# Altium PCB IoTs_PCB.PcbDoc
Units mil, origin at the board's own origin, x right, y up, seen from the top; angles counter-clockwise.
Board outline 3940 x 3935 mil, 2 copper layers (Top Layer, Bottom Layer); 12 components, 13 nets, 57 pads, 0 vias.
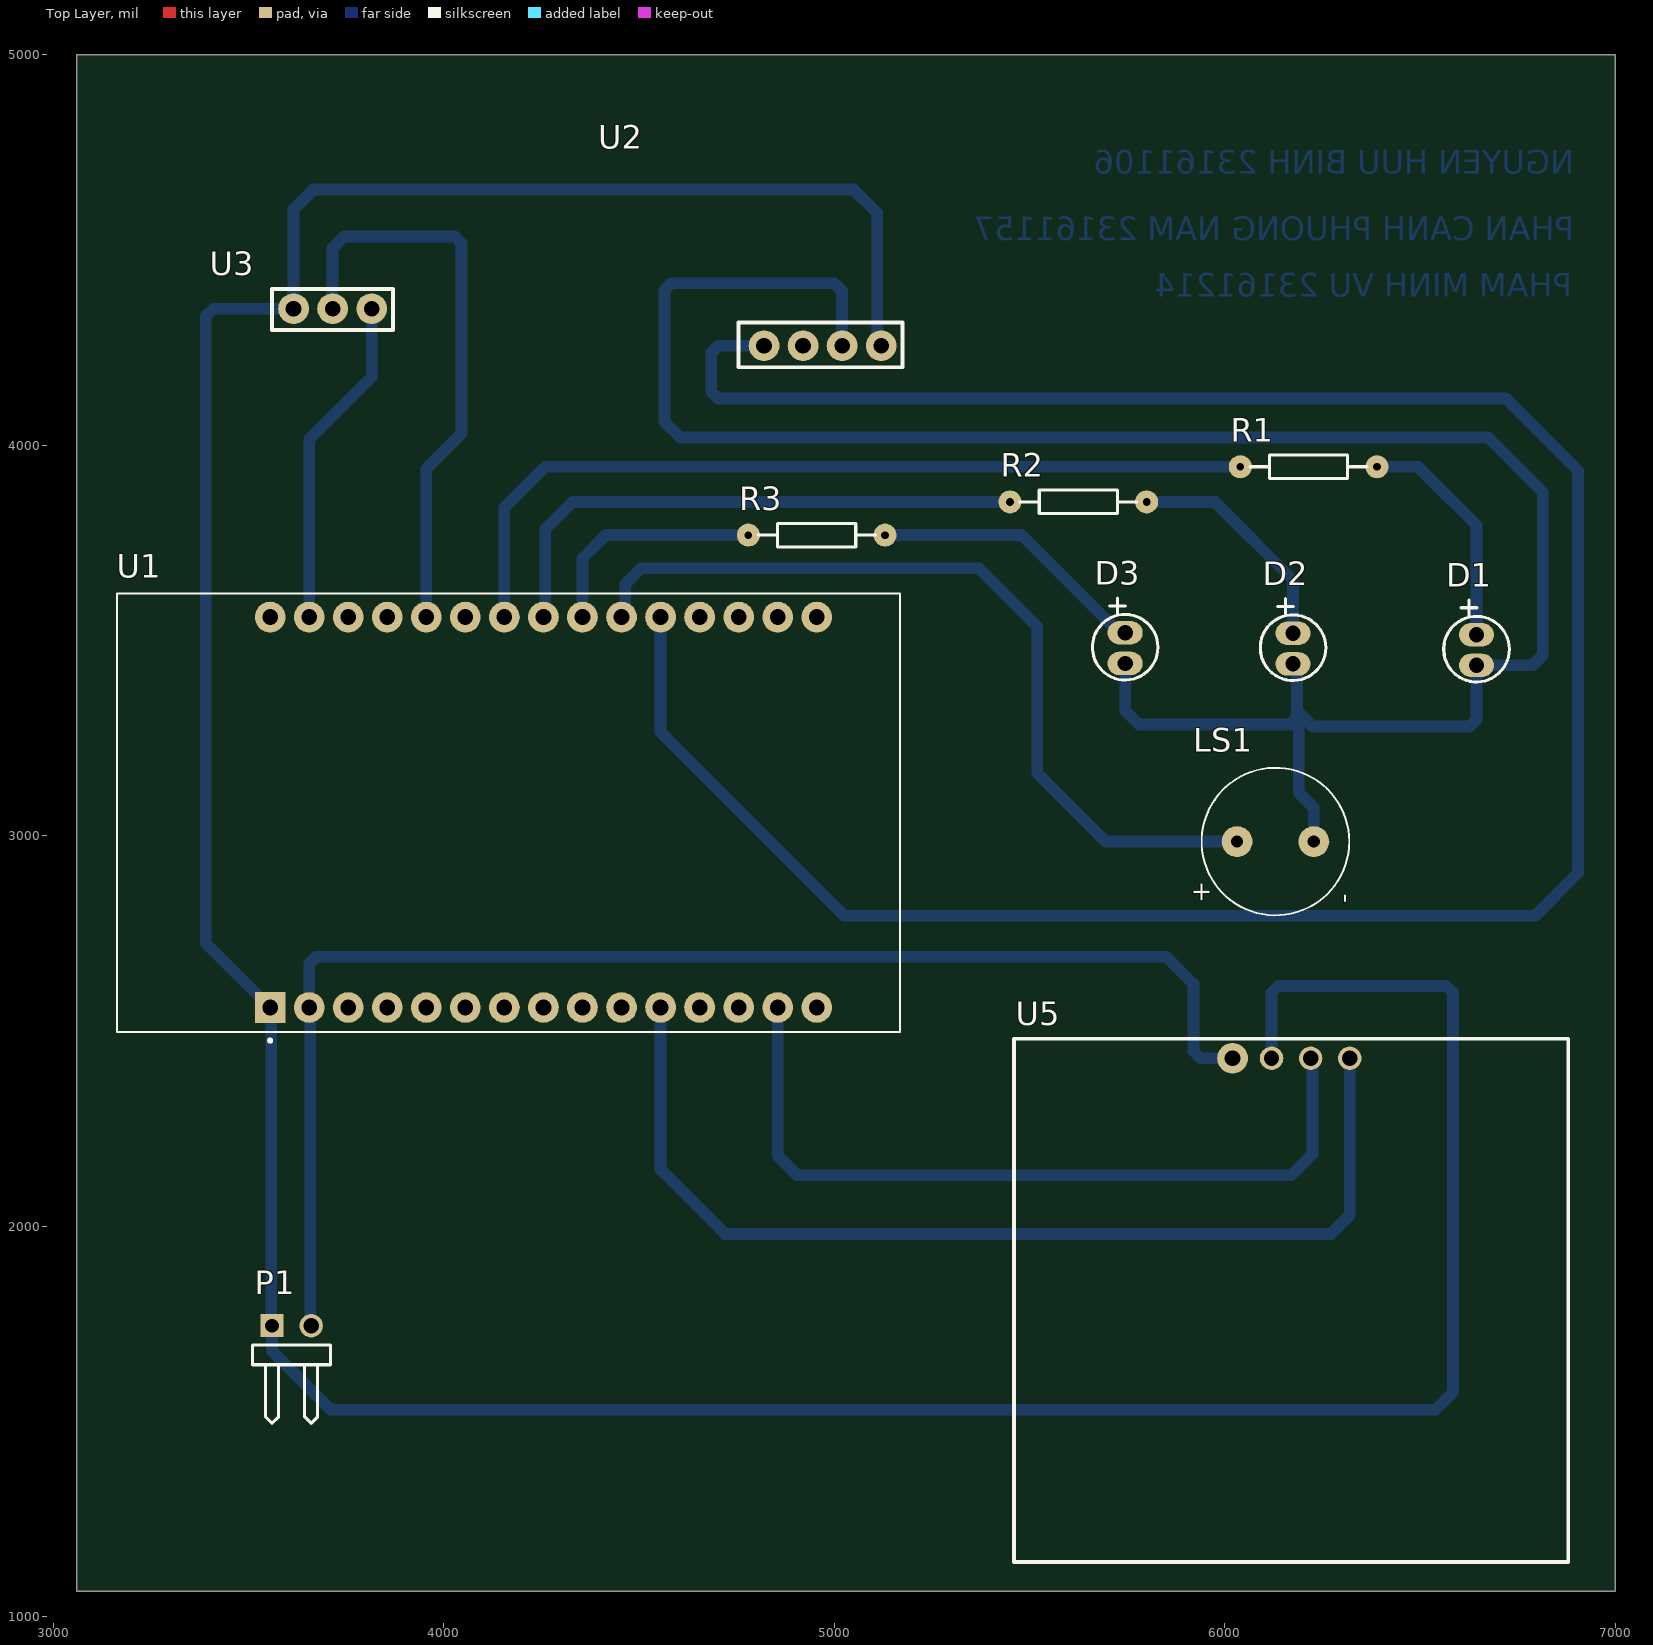
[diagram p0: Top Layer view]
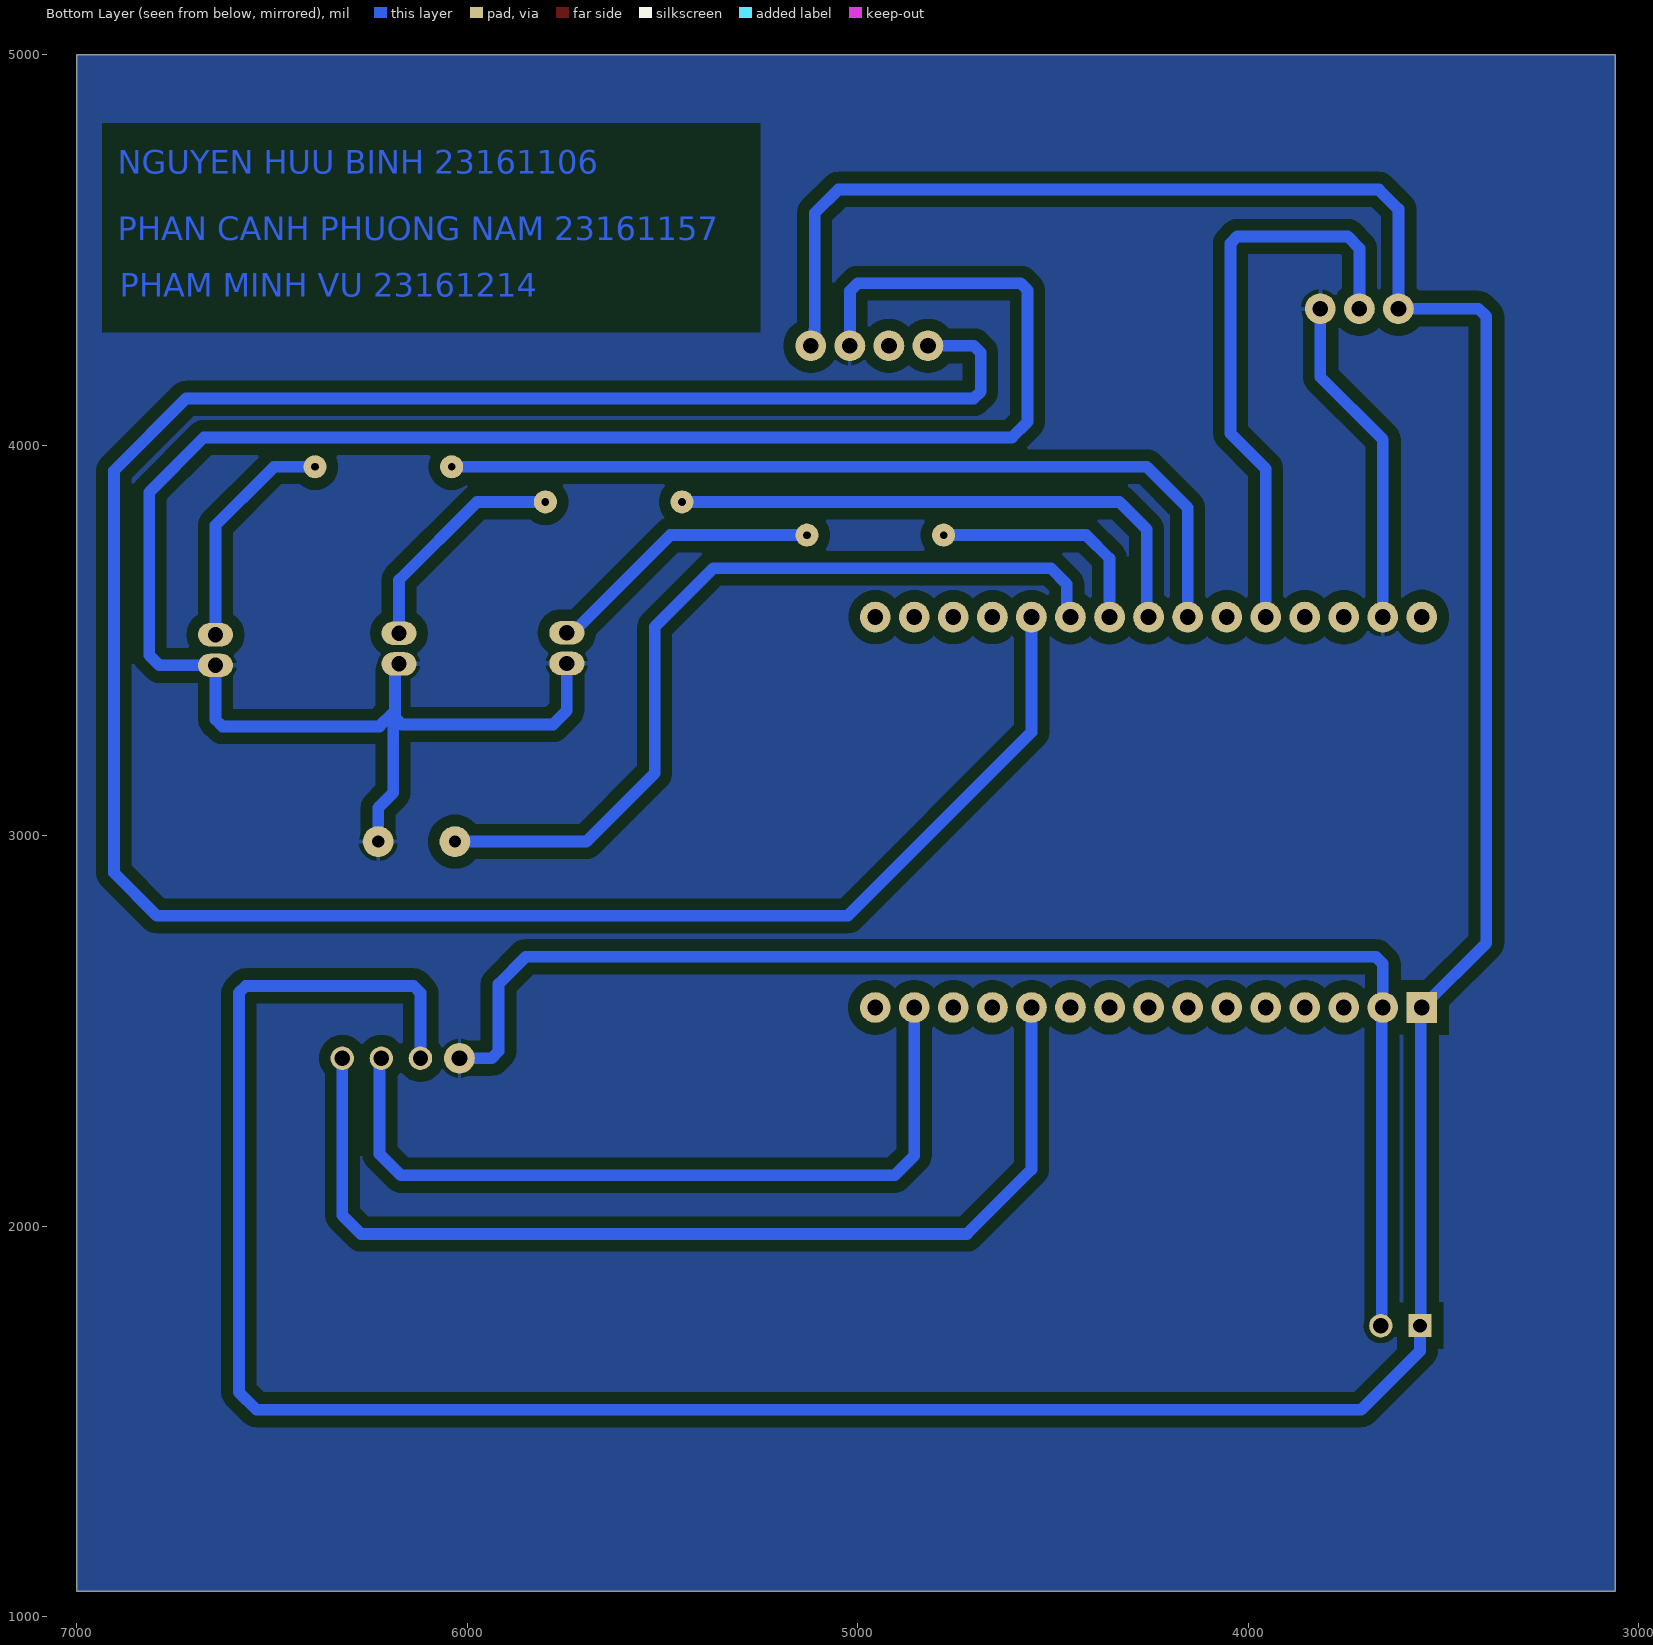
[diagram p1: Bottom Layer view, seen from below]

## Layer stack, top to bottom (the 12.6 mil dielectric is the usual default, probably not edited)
Top Solder: solder mask 0.4, Solder Resist, Dk 3.5
Top Layer: signal copper 1.4
Dielectric 1: dielectric 12.6, FR-4, Dk 4.8
Bottom Layer: signal copper 1.4
Bottom Solder: solder mask 0.4, Solder Resist, Dk 3.5

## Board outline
3060,1065 7000,1065 7000,5000 3060,5000

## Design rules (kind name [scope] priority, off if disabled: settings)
Clearance [All] p1: gap=10 ignorepadtopadclearanceinfootprint=FALSE except(30: Arc-Fill Arc-Poly Arc-Region Track-Fill Track-Poly Track-Region SMDPad-Fill SMDPad-Poly SMDPad-Region THPad-Fill THPad-Poly THPad-Region Via-Fill Via-Poly Via-Region Fill-Fill Fill-Poly Fill-Region Poly-Poly Poly-Region Region-Region)
PolygonConnect [All] p1: connectstyle=Relief reliefconductorwidth=10 reliefentries=4 polygonreliefangle="90 Angle" airgapwidth=10
RoutingLayers [All] p1: top layer_v5=FALSE bottom layer_v5=TRUE
RoutingVias [All] p1: holewidth=28 width=50 viastyle="Through Hole" minholewidth=28 minwidth=50 maxholewidth=28 maxwidth=50
SolderMaskExpansion [All] p1: expansion=4 istentingtop=FALSE
Width [All] p1: maxlimit=50 minlimit=28 preferedwidth=30
29 further rules are at their usual default settings.

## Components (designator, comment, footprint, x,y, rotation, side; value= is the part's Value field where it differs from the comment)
D1 "LED" CAP10UF 6645,3436.26 r90 top
D2 "LED" CAP10UF 6175,3440 r90 top
D3 "LED" CAP10UF 5745,3441.26 r90 top
LS1 "CMI-9605IC-0580T" CUI_CMI-9605IC-0580T 6130,2985 r90 top
P1 "Header 2H" HDR1X2H 3560,1745 r0 top
R1 "220" R1/6W 6215,3945 r0 top value="R1/4W - 1K"
R2 "220" R1/6W 5625,3855 r0 top value="R1/4W - 1K"
R3 "220" R1/6W 4955,3770 r0 top value="R1/4W - 1K"
U1 "ESP32_DEVKIT_V1" ESP32_DEVKIT_V1 4190.83,3045 r90 top
U2 "MQ_135" MQ_135 4820,4255 r0 top
U3 "DHT11" DHT11 3615,4350 r0 top
U5 "LCD OLED SSD1306" "LCD SH1106" 6235,1735 r0 top

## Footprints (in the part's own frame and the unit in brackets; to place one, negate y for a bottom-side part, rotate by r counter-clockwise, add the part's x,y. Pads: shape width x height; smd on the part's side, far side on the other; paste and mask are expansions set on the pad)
CAP10UF [mil]
  oval 60x90 hole 39.37 unplated: 1(78.74,0) 2(0,0)
  silkscreen extent -42,-84 167,84
CUI_CMI-9605IC-0580T [mm]
  round 2 hole 0.8: N(0,-2.5) P(0,2.5)
  silkscreen extent -4.8,-4.8 4.8,4.8, body extent -4.8,-4.8 4.8,4.8
DHT11 [mm]
  round 2 hole 1.02: 1(0,0) 2(2.54,0) 3(5.08,0)
  silkscreen extent -1.4,-1.4 6.48,1.27, body extent -5.71,-7.49 10.29,1.01, height 24.09
ESP32_DEVKIT_V1 [mm]
  rect 2x2 / inner round 2 / far side rect 2x2 hole 1.02: 1(-12.319,16.15)
  round 2 hole 1.02: 2(-12.319,13.61) 3(-12.319,11.07) 4(-12.319,8.53) 5(-12.319,5.99) 6(-12.319,3.45) 7(-12.319,0.91) 8(-12.319,-1.63) 9(-12.319,-4.17) 10(-12.319,-6.71) 11(-12.319,-9.25) 12(-12.319,-11.79) 13(-12.319,-14.33) 14(-12.319,-16.87) 15(-12.319,-19.41) 16(13.081,-19.41) 17(13.081,-16.87) 18(13.081,-14.33) 19(13.081,-11.79) 20(13.081,-9.25) 21(13.081,-6.71) 22(13.081,-4.17) 23(13.081,-1.63) 24(13.081,0.91) 25(13.081,3.45) 26(13.081,5.99) 27(13.081,8.53) 28(13.081,11.07) 29(13.081,13.61) 30(13.081,16.15)
  silkscreen extent -14.57,-24.84 14.61,26.11
HDR1X2H [mm] "Connector; Header; 2 Position; Right Angle"
  rect 1.5x1.5 hole 0.9: 1(0,0)
  round 1.524 hole 1.02: 2(2.54,0)
  silkscreen extent -1.27,-6.35 3.81,-1.27, body extent -1.27,-7 3.81,1.27, height 4.33
"LCD SH1106" [mil]
  round 60 hole 39.37: 1(85,695) 2(-15,695) 3(-115,695)
  round 78.74 hole 40.16: 4(-215,695)
  silkscreen extent -775,-595 645,745, body extent -774,-594 644,744, height 378
MQ_135 [mm]
  round 2 hole 1.02: 1(7.62,0) 2(5.08,0) 3(2.54,0) 4(0,0)
  silkscreen extent -1.65,-1.4 9.02,1.52, body extent -6.75,-4.99 14.25,18.01, height 1.5
R1/6W [mm]
  round 1.5 hole 0.5: 1(-4.445,0) 2(4.445,0)
  silkscreen extent -3.81,-0.76 3.81,0.76

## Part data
LS1: "9.6 mm, 5 Vdc, 80 dB, Through Hole, Driving Circuit, Magnetic Audio Indicator Buzzer", Package=Package
P1: "Header, 2-Pin, Right Angle"
R1 R2 R3: library part Res, "Resistor 1/4W"
U5: library part "LCD SH1106"

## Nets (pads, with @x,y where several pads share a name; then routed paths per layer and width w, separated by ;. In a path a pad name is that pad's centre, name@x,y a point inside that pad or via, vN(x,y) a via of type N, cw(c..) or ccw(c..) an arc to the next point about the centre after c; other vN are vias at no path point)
A0: U1.20 U2.4 | length 6461.3
  Bottom Layer w30: U1.20 4555,3265 5025,2795 6795,2795 6905,2905 6905,3935 6720,4120 4702.57,4120 4685,4137.57 4685,4237.43 4702.57,4255 U2.4
DAT: U1.26 U3.2 | length 1499.4
  Bottom Layer w30: U3.2 3715,4505 3745,4535 4027.43,4535 4045,4517.43 4045,4030 3955,3940 U1.26
GND: D1.2 D2.2 D3.2 LS1.N P1.2 U1.2 U1.29 U2.2 U3.3 U5.4 | length 9926
  Bottom Layer w30: U1.29 3655,4015 3815,4175 U3.3 ; P1.2 3657.5,1747.5 3657.5,2557.5 U1.2 3655,2672.43 3672.57,2690 5850,2690 5920,2620 5920,2447.57 5937.57,2430 U5.4 ; U2.2 5020,4395 5000,4415 4582.57,4415 4565,4397.43 4565,4060 4605,4020 6675,4020 6815,3880 6815,3462.57 6788.69,3436.26 D1.2 6645,3297.57 6627.43,3280 6225,3280 6190,3315 ; D3.2 5745,3320 5780,3285 6167.43,3285 6182.88,3300.45 ; D2.2 6185,3430 6185,3302.57 ; 6188,3310.03 6190,3315 ; LS1.N 6228.43,3071.57 6190,3110 6190,3300.45 6190,3315
GREEN: R3.1 U1.22 | length 599.9
  Bottom Layer w30: U1.22 4355,3710 4415,3770 R3.1
LS1: LS1.P U1.21 | length 2181.9
  Bottom Layer w30: U1.21 4464.33,3569.33 4464.33,3644.33 4505,3685 5370,3685 5384.99,3670.01 5520,3535 5520,3160 5695,2985 LS1.P
NetD1_1: D1.1 R1.2 | length 597.1
  Bottom Layer w30: R1.2 6495,3945 6509.99,3930.01 6645,3795 D1.1
NetD2_1: D2.1 R2.2 | length 594.1
  Bottom Layer w30: R2.2 5975,3855 6175,3655 D2.1
NetD3_1: D3.1 R3.2 | length 718.6
  Bottom Layer w30: R3.2 5480,3770 5730,3520 D3.1
RED: R1.1 U1.24 | length 2208.5
  Bottom Layer w30: U1.24 4155,3840 4260,3945 R1.1
SCL: U1.14 U5.2 | length 2040.6
  Bottom Layer w30: U1.14 4855,2180 4905,2130 6170,2130 6225,2185 6225,2425 U5.2
SDA: U1.11 U5.1 | length 2670.5
  Bottom Layer w30: U1.11 4555,2145 4720,1980 6272.43,1980 6320,2027.57 U5.1
VCC: P1.1 U1.1 U2.1 U3.1 U5.3 | length 9868.6
  Bottom Layer w30: U2.1 5110.67,4264.33 5110.67,4296.27 5110,4296.94 5110,4595 5050,4655 3665,4655 3615,4605 U3.1 3410,4350 3390,4330 3390,2725 U1.1 3557.5,2557.5 3557.5,1747.5 P1.1 3560,1680 3710,1530 6540,1530 6585,1575 6585,2597.43 6567.43,2615 6137.57,2615 6120,2597.43 U5.3
YELLOW: R2.1 U1.23 | length 1446.1
  Bottom Layer w30: U1.23 4260,3565 4260,3785 4330,3855 R2.1
pads on no net: U1.3 U1.4 U1.5 U1.6 U1.7 U1.8 U1.9 U1.10 U1.12 U1.13 U1.15 U1.16 U1.17 U1.18 U1.19 U1.25 U1.27 U1.28 U1.30 U2.3

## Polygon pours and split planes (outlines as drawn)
GND on Bottom Layer "GND_L02_P000" (solid, pour order 0): 3060,5000 7000,5000 7000,1065 3060,1065

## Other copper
Bottom Layer:
  pour cut-out: 5250,4825 6935,4825 6935,4290 5250,4290
  text "NGUYEN HUU BINH 23161106" at 6895,4695 h60
  text "PHAN CANH PHUONG NAM 23161157" at 6895,4525 h60
  text "PHAM MINH VU 23161214" at 6890,4380 h60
